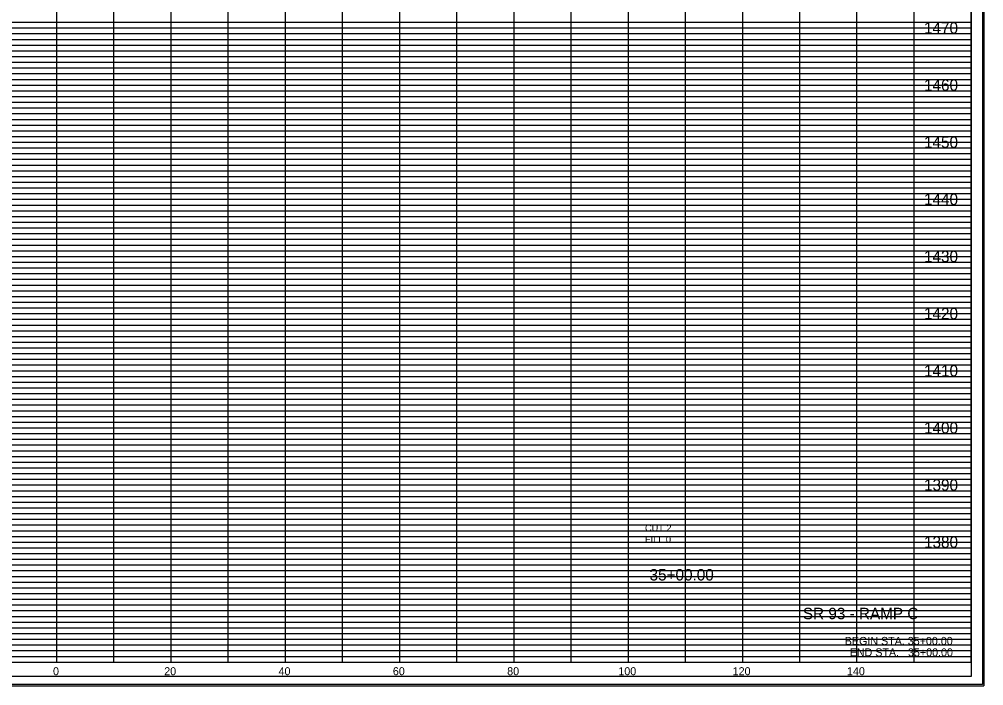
# Model space of a CAD drawing. Extents: x 980 to 2064, y 978 to 2267.
# Drawn here: x 1893.4 to 2062.2, y 1515.9 to 1632.5 of the extents above; entities that cross this region are included whole.
import ezdxf

# ---------------------------------------------------------------- set-up
doc = ezdxf.new("R2010")
doc.units = 0
for name, color, linetype in [('Default', 7, 'Continuous'), ('DESIGN - SHEET - Corner Text', 7, 'Continuous'), ('DESIGN - SHEET - Light Grid', 7, 'Continuous'), ('DESIGN - SHEET - Linework', 7, 'Continuous'), ('DESIGN - SHEET - Plot Shape', 7, 'Continuous'), ('DESIGN - TYPICAL - Text', 7, 'Continuous')]:
    doc.layers.add(name, color=color, linetype=linetype)

# ---------------------------------------------------------------- blocks, each defined once
blk = doc.blocks.new('XSTSHT')
at = {"layer": 'DESIGN - SHEET - Light Grid'}
for p, q in [((8, 11.2), (16, 11.2)), ((16, 11.2), (24, 11.2)), ((24, 11.2), (32, 11.2)), ((8, 11.1), (16, 11.1)), ((16, 11.1), (24, 11.1)), ((24, 11.1), (32, 11.1)), ((8, 10.9), (16, 10.9)), ((8, 10.8), (16, 10.8)), ((16, 10.9), (24, 10.9)), ((16, 10.8), (24, 10.8)), ((24, 10.9), (32, 10.9)), ((24, 10.8), (32, 10.8)), ((8, 10.7), (16, 10.7)), ((16, 10.7), (24, 10.7)), ((24, 10.7), (32, 10.7)), ((8, 10.6), (16, 10.6)), ((8, 10.5), (16, 10.5)), ((16, 10.6), (24, 10.6)), ((16, 10.5), (24, 10.5)), ((24, 10.6), (32, 10.6)), ((24, 10.5), (32, 10.5)), ((8, 10.4), (16, 10.4)), ((8, 10.3), (16, 10.3)), ((16, 10.4), (24, 10.4)), ((16, 10.3), (24, 10.3)), ((24, 10.4), (32, 10.4)), ((24, 10.3), (32, 10.3)), ((8, 10.2), (16, 10.2)), ((16, 10.2), (24, 10.2)), ((24, 10.2), (32, 10.2)), ((8, 10.1), (16, 10.1)), ((16, 10.1), (24, 10.1)), ((24, 10.1), (32, 10.1)), ((8, 9.9), (16, 9.9)), ((8, 9.8), (16, 9.8)), ((16, 9.9), (24, 9.9)), ((16, 9.8), (24, 9.8)), ((24, 9.9), (32, 9.9)), ((24, 9.8), (32, 9.8)), ((8, 9.7), (16, 9.7)), ((16, 9.7), (24, 9.7)), ((24, 9.7), (32, 9.7)), ((8, 9.6), (16, 9.6)), ((8, 9.5), (16, 9.5)), ((16, 9.6), (24, 9.6)), ((16, 9.5), (24, 9.5)), ((24, 9.6), (32, 9.6)), ((24, 9.5), (32, 9.5)), ((8, 9.4), (16, 9.4)), ((8, 9.3), (16, 9.3)), ((16, 9.4), (24, 9.4)), ((16, 9.3), (24, 9.3)), ((24, 9.4), (32, 9.4)), ((24, 9.3), (32, 9.3)), ((8, 9.2), (16, 9.2)), ((16, 9.2), (24, 9.2)), ((24, 9.2), (32, 9.2)), ((8, 9.1), (16, 9.1)), ((16, 9.1), (24, 9.1)), ((24, 9.1), (32, 9.1)), ((8, 8.9), (16, 8.9)), ((8, 8.8), (16, 8.8)), ((16, 8.9), (24, 8.9)), ((16, 8.8), (24, 8.8)), ((24, 8.9), (32, 8.9)), ((24, 8.8), (32, 8.8)), ((8, 8.7), (16, 8.7)), ((16, 8.7), (24, 8.7)), ((24, 8.7), (32, 8.7)), ((8, 8.6), (16, 8.6)), ((8, 8.5), (16, 8.5)), ((16, 8.6), (24, 8.6)), ((16, 8.5), (24, 8.5)), ((24, 8.6), (32, 8.6)), ((24, 8.5), (32, 8.5)), ((8, 8.4), (16, 8.4)), ((8, 8.3), (16, 8.3)), ((16, 8.4), (24, 8.4)), ((16, 8.3), (24, 8.3)), ((24, 8.4), (32, 8.4)), ((24, 8.3), (32, 8.3)), ((8, 8.2), (16, 8.2)), ((8, 8.1), (16, 8.1)), ((16, 8.2), (24, 8.2)), ((16, 8.1), (24, 8.1)), ((24, 8.2), (32, 8.2)), ((24, 8.1), (32, 8.1)), ((8, 7.9), (16, 7.9)), ((8, 7.8), (16, 7.8)), ((16, 7.9), (24, 7.9)), ((16, 7.8), (24, 7.8)), ((24, 7.9), (32, 7.9)), ((24, 7.8), (32, 7.8)), ((8, 7.7), (16, 7.7)), ((8, 7.6), (16, 7.6)), ((16, 7.7), (24, 7.7)), ((16, 7.6), (24, 7.6)), ((24, 7.7), (32, 7.7)), ((24, 7.6), (32, 7.6)), ((8, 7.5), (16, 7.5)), ((16, 7.5), (24, 7.5)), ((24, 7.5), (32, 7.5)), ((8, 7.4), (16, 7.4)), ((8, 7.3), (16, 7.3)), ((16, 7.4), (24, 7.4)), ((16, 7.3), (24, 7.3)), ((24, 7.4), (32, 7.4)), ((24, 7.3), (32, 7.3)), ((8, 7.2), (16, 7.2)), ((8, 7.1), (16, 7.1)), ((16, 7.2), (24, 7.2)), ((16, 7.1), (24, 7.1)), ((24, 7.2), (32, 7.2)), ((24, 7.1), (32, 7.1)), ((8, 6.9), (16, 6.9)), ((8, 6.8), (16, 6.8)), ((16, 6.9), (24, 6.9)), ((16, 6.8), (24, 6.8)), ((24, 6.9), (32, 6.9)), ((24, 6.8), (32, 6.8)), ((8, 6.7), (16, 6.7)), ((8, 6.6), (16, 6.6)), ((16, 6.7), (24, 6.7)), ((16, 6.6), (24, 6.6)), ((24, 6.7), (32, 6.7)), ((24, 6.6), (32, 6.6)), ((8, 6.5), (16, 6.5)), ((16, 6.5), (24, 6.5)), ((24, 6.5), (32, 6.5)), ((8, 6.4), (16, 6.4)), ((8, 6.3), (16, 6.3)), ((16, 6.4), (24, 6.4)), ((16, 6.3), (24, 6.3)), ((24, 6.4), (32, 6.4)), ((24, 6.3), (32, 6.3)), ((8, 6.2), (16, 6.2)), ((8, 6.1), (16, 6.1)), ((16, 6.2), (24, 6.2)), ((16, 6.1), (24, 6.1)), ((24, 6.2), (32, 6.2)), ((24, 6.1), (32, 6.1)), ((8, 5.9), (16, 5.9)), ((8, 5.8), (16, 5.8)), ((16, 5.9), (24, 5.9)), ((16, 5.8), (24, 5.8)), ((24, 5.9), (32, 5.9)), ((24, 5.8), (32, 5.8)), ((8, 5.7), (16, 5.7)), ((8, 5.6), (16, 5.6)), ((16, 5.7), (24, 5.7)), ((16, 5.6), (24, 5.6)), ((24, 5.7), (32, 5.7)), ((24, 5.6), (32, 5.6)), ((8, 5.5), (16, 5.5)), ((8, 5.4), (16, 5.4)), ((16, 5.5), (24, 5.5)), ((16, 5.4), (24, 5.4)), ((24, 5.5), (32, 5.5)), ((24, 5.4), (32, 5.4)), ((8, 5.3), (16, 5.3)), ((16, 5.3), (24, 5.3)), ((24, 5.3), (32, 5.3)), ((8, 5.2), (16, 5.2)), ((8, 5.1), (16, 5.1)), ((16, 5.2), (24, 5.2)), ((16, 5.1), (24, 5.1)), ((24, 5.2), (32, 5.2)), ((24, 5.1), (32, 5.1)), ((8, 4.9), (16, 4.9)), ((16, 4.9), (24, 4.9)), ((24, 4.9), (32, 4.9)), ((8, 4.8), (16, 4.8)), ((16, 4.8), (24, 4.8)), ((24, 4.8), (32, 4.8)), ((8, 4.7), (16, 4.7)), ((8, 4.6), (16, 4.6)), ((16, 4.7), (24, 4.7)), ((16, 4.6), (24, 4.6)), ((24, 4.7), (32, 4.7)), ((24, 4.6), (32, 4.6)), ((8, 4.5), (16, 4.5)), ((8, 4.4), (16, 4.4)), ((16, 4.5), (24, 4.5)), ((16, 4.4), (24, 4.4)), ((24, 4.5), (32, 4.5)), ((24, 4.4), (32, 4.4)), ((8, 4.3), (16, 4.3)), ((16, 4.3), (24, 4.3)), ((24, 4.3), (32, 4.3)), ((8, 4.2), (16, 4.2)), ((8, 4.1), (16, 4.1)), ((16, 4.2), (24, 4.2)), ((16, 4.1), (24, 4.1)), ((24, 4.2), (32, 4.2)), ((24, 4.1), (32, 4.1)), ((8, 3.9), (16, 3.9)), ((16, 3.9), (24, 3.9)), ((24, 3.9), (32, 3.9)), ((8, 3.8), (16, 3.8)), ((16, 3.8), (24, 3.8)), ((24, 3.8), (32, 3.8)), ((8, 3.7), (16, 3.7)), ((8, 3.6), (16, 3.6)), ((16, 3.7), (24, 3.7)), ((16, 3.6), (24, 3.6)), ((24, 3.7), (32, 3.7)), ((24, 3.6), (32, 3.6)), ((8, 3.5), (16, 3.5)), ((8, 3.4), (16, 3.4)), ((16, 3.5), (24, 3.5)), ((16, 3.4), (24, 3.4)), ((24, 3.5), (32, 3.5)), ((24, 3.4), (32, 3.4)), ((8, 3.3), (16, 3.3)), ((16, 3.3), (24, 3.3)), ((24, 3.3), (32, 3.3)), ((8, 3.2), (16, 3.2)), ((8, 3.1), (16, 3.1)), ((16, 3.2), (24, 3.2)), ((16, 3.1), (24, 3.1)), ((24, 3.2), (32, 3.2)), ((24, 3.1), (32, 3.1)), ((8, 2.9), (16, 2.9)), ((16, 2.9), (24, 2.9)), ((24, 2.9), (32, 2.9)), ((8, 2.8), (16, 2.8)), ((8, 2.7), (16, 2.7)), ((16, 2.8), (24, 2.8)), ((16, 2.7), (24, 2.7)), ((24, 2.8), (32, 2.8)), ((24, 2.7), (32, 2.7)), ((8, 2.6), (16, 2.6)), ((16, 2.6), (24, 2.6)), ((24, 2.6), (32, 2.6)), ((8, 2.5), (16, 2.5)), ((8, 2.4), (16, 2.4)), ((16, 2.5), (24, 2.5)), ((16, 2.4), (24, 2.4)), ((24, 2.5), (32, 2.5)), ((24, 2.4), (32, 2.4)), ((8, 2.3), (16, 2.3)), ((8, 2.2), (16, 2.2)), ((16, 2.3), (24, 2.3)), ((16, 2.2), (24, 2.2)), ((24, 2.3), (32, 2.3)), ((24, 2.2), (32, 2.2)), ((8, 2.1), (16, 2.1)), ((16, 2.1), (24, 2.1)), ((24, 2.1), (32, 2.1)), ((8, 1.9), (16, 1.9)), ((16, 1.9), (24, 1.9)), ((24, 1.9), (32, 1.9)), ((8, 1.8), (16, 1.8)), ((8, 1.7), (16, 1.7)), ((16, 1.8), (24, 1.8)), ((16, 1.7), (24, 1.7)), ((24, 1.8), (32, 1.8)), ((24, 1.7), (32, 1.7)), ((8, 1.6), (16, 1.6)), ((16, 1.6), (24, 1.6)), ((24, 1.6), (32, 1.6)), ((8, 1.5), (16, 1.5)), ((8, 1.4), (16, 1.4)), ((16, 1.5), (24, 1.5)), ((16, 1.4), (24, 1.4)), ((24, 1.5), (32, 1.5)), ((24, 1.4), (32, 1.4)), ((8, 1.3), (16, 1.3)), ((8, 1.2), (16, 1.2)), ((16, 1.3), (24, 1.3)), ((16, 1.2), (24, 1.2)), ((24, 1.3), (32, 1.3)), ((24, 1.2), (32, 1.2)), ((8, 1.1), (16, 1.1)), ((16, 1.1), (24, 1.1)), ((24, 1.1), (32, 1.1)), ((8, 0.9), (16, 0.9)), ((16, 0.9), (24, 0.9)), ((24, 0.9), (32, 0.9)), ((8, 0.8), (16, 0.8)), ((8, 0.7), (16, 0.7)), ((16, 0.8), (24, 0.8)), ((16, 0.7), (24, 0.7)), ((24, 0.8), (32, 0.8)), ((24, 0.7), (32, 0.7)), ((8, 0.6), (16, 0.6)), ((16, 0.6), (24, 0.6)), ((24, 0.6), (32, 0.6)), ((8, 0.5), (16, 0.5)), ((8, 0.4), (16, 0.4)), ((16, 0.5), (24, 0.5)), ((16, 0.4), (24, 0.4)), ((24, 0.5), (32, 0.5)), ((24, 0.4), (32, 0.4)), ((8, 0.3), (16, 0.3)), ((8, 0.2), (16, 0.2)), ((16, 0.3), (24, 0.3)), ((16, 0.2), (24, 0.2)), ((24, 0.3), (32, 0.3)), ((24, 0.2), (32, 0.2)), ((8, 0.1), (16, 0.1)), ((16, 0.1), (24, 0.1)), ((24, 0.1), (32, 0.1))]:
    blk.add_line(p, q, dxfattribs=at)
at = {"layer": 'DESIGN - SHEET - Linework'}
for p, q in [((32.217, 21.414), (32.217, -0.414)), ((16, 0), (16, 21)), ((17, 0), (17, 21)), ((18, 0), (18, 21)), ((19, 0), (19, 21)), ((20, 0), (20, 21)), ((21, 0), (21, 21)), ((22, 0), (22, 21)), ((23, 0), (23, 21)), ((24, 0), (24, 21)), ((25, 0), (25, 21)), ((26, 0), (26, 21)), ((27, 0), (27, 21)), ((28, 0), (28, 20)), ((29, 0), (29, 20)), ((30, 0), (30, 20)), ((31, 0), (31, 20)), ((0, 11), (32, 11)), ((0, 10), (32, 10)), ((0, 9), (32, 9)), ((0, 8), (32, 8)), ((0, 7), (32, 7)), ((0, 6), (32, 6)), ((0, 5), (32, 5)), ((0, 4), (32, 4)), ((0, 3), (32, 3)), ((0, 2), (32, 2)), ((0, 1), (32, 1)), ((-1.823, -0.414), (32.217, -0.414))]:
    blk.add_line(p, q, dxfattribs=at)
blk.add_lwpolyline([(0, 21), (0, 0), (32, 0), (32, 21), (0, 21)], dxfattribs=at)
at = {"layer": 'DESIGN - SHEET - Plot Shape'}
for points in [[(-1.803, 21.394), (32.197, 21.394), (32.197, -0.394), (-1.803, -0.394)], [(-0.85, 21), (32, 21), (32, -0.25), (-0.85, -0.25)]]:
    blk.add_lwpolyline(points, close=True, dxfattribs=at)

msp = doc.modelspace()

# ---------------------------------------------------------------- block references
at = {"layer": 'Default', "xscale": 10, "yscale": 10}
msp.add_blockref('XSTSHT', (1740, 1520), dxfattribs=at)

# ---------------------------------------------------------------- texts
at = {"layer": 'Default'}
for s, height, p in [('     1470     ', 2, (2048.01, 1630)), ('     1460     ', 2, (2048.01, 1620)), ('     1450     ', 2, (2048.01, 1610)), ('     1440     ', 2, (2048.01, 1600)), ('     1430     ', 2, (2048.01, 1590)), ('     1420     ', 2, (2048.01, 1580)), ('     1410     ', 2, (2048.01, 1570)), ('     1400     ', 2, (2048.01, 1560)), ('     1390     ', 2, (2048.01, 1550)), ('     1380     ', 2, (2048.01, 1540)), ('     35+00.00     ', 2, (2000, 1534.28)), ('     0     ', 1.4, (1896.74, 1517.7)), ('     0     ', 1.4, (1896.74, 1517.7)), ('     20     ', 1.4, (1916.2, 1517.7)), ('     40     ', 1.4, (1936.2, 1517.7)), ('     60     ', 1.4, (1956.2, 1517.7)), ('     80     ', 1.4, (1976.2, 1517.7)), ('     100     ', 1.4, (1995.65, 1517.7)), ('     120     ', 1.4, (2015.65, 1517.7)), ('     140     ', 1.4, (2035.65, 1517.7))]:
    msp.add_text(s, height=height, dxfattribs=at).set_placement(p)
at = {"layer": 'DESIGN - SHEET - Corner Text'}
for s, height, p in [('SR 93 - RAMP C', 2, (2030.53, 1527.5)), ('BEGIN STA. 35+00.00', 1.4, (2037.86, 1523)), ('END STA.   35+00.00', 1.4, (2038.73, 1521))]:
    msp.add_text(s, height=height, dxfattribs=at).set_placement(p)
at = {"layer": 'DESIGN - TYPICAL - Text'}
for s, p in [('CUT 2', (2002.91, 1542.87)), ('FILL 0', (2002.91, 1540.87))]:
    msp.add_text(s, height=1.2, dxfattribs=at).set_placement(p)

doc.saveas('drawing.dxf')
